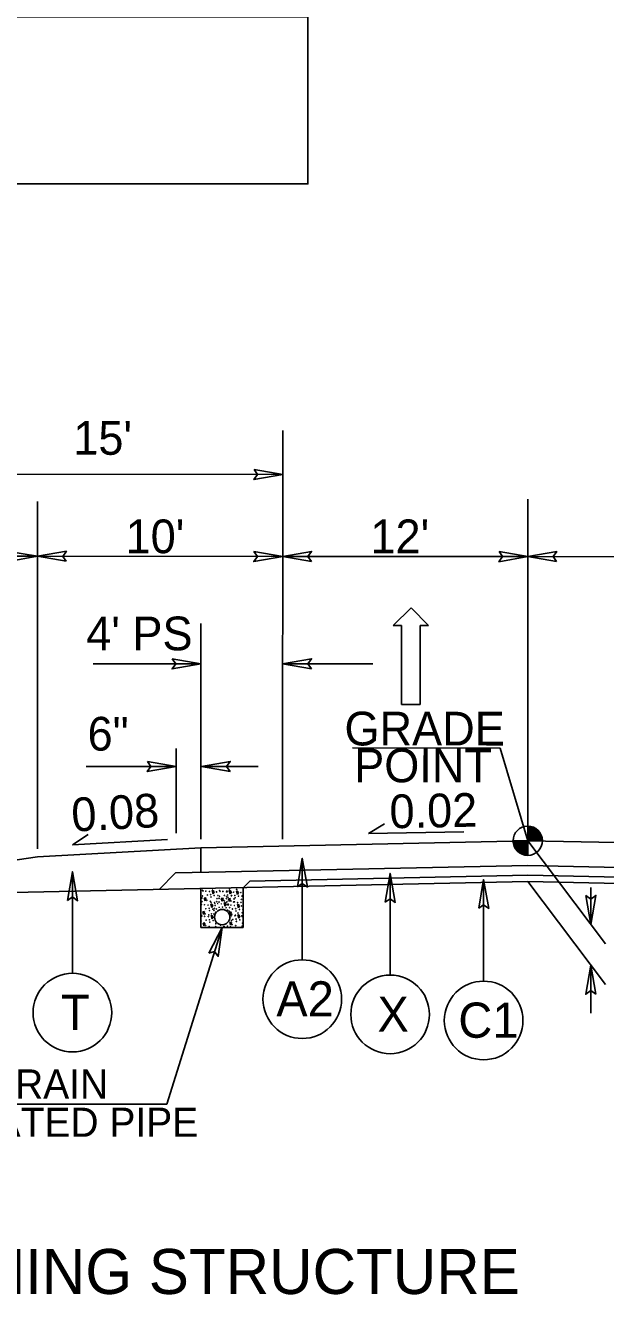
# Model space of a CAD drawing. Extents: x 2241081 to 2251104, y 658534 to 663427.
# Drawn here: x 2243735.8 to 2243877.8, y 662105.6 to 662416.1 of the extents above; entities that cross this region are included whole.
import ezdxf

# ---------------------------------------------------------------- set-up
doc = ezdxf.new("R2010")
doc.units = 0
for name, color, linetype in [('Old_Level_1', 7, 'Continuous'), ('Old_Level_11', 7, 'Continuous'), ('Old_Level_2', 7, 'Continuous'), ('Old_Level_3', 7, 'Continuous'), ('Prop Dimension Text', 7, 'Continuous'), ('Prop Lane Arrow CELL', 7, 'Continuous'), ('Prop Pavement Schedule Description CELL', 7, 'Continuous'), ('Typical Arrow Superelevation CELL', 7, 'Continuous'), ('Typical Berm Information CELL', 7, 'Continuous'), ('Typical Curb CELL', 7, 'Continuous'), ('Typical Grade Point Symbol CELL', 7, 'Continuous'), ('Typical ID Circle CELL', 7, 'Continuous'), ('Typical Terminator CELL', 7, 'Continuous'), ('Typical Text Grade Point CELL', 7, 'Continuous'), ('Typical Text ID Circle CELL', 7, 'Continuous'), ('Typical Text Label CELL', 7, 'Continuous')]:
    doc.layers.add(name, color=color, linetype=linetype)

msp = doc.modelspace()

# ---------------------------------------------------------------- linework, layer by layer
at = {"layer": 'Old_Level_1'}
msp.add_line((2243738.73, 662212.77), (2243713.82, 662209.11), dxfattribs=at)
at = {"layer": 'Old_Level_11'}
msp.add_line((2243770.41, 662152.21), (2243783.94, 662195.49), dxfattribs=at)
at = {"layer": 'Old_Level_2'}
for p, q in [((2243778.73, 662214.97), (2243738.73, 662212.77)), ((2243858.73, 662216.68), (2243778.73, 662214.97)), ((2243778.73, 662214.97), (2243778.73, 662208.92)), ((2243858.73, 662216.68), (2243968.73, 662214.33)), ((2243772.55, 662208.79), (2243768.51, 662204.75)), ((2243784.76, 662209.05), (2243772.55, 662208.79)), ((2243858.73, 662210.63), (2243784.76, 662209.05)), ((2243858.73, 662208.27), (2243790.77, 662206.82)), ((2243858.73, 662210.63), (2243947.95, 662208.72)), ((2243858.73, 662208.27), (2243956.82, 662206.17)), ((2243858.73, 662206.68), (2243713.77, 662203.58)), ((2243778.73, 662204.97), (2243778.73, 662195.49)), ((2243790.77, 662206.82), (2243789.14, 662205.19)), ((2243789.14, 662205.19), (2243789.14, 662195.49)), ((2243858.73, 662206.68), (2243978.95, 662204.11)), ((2243778.73, 662195.49), (2243789.14, 662195.49))]:
    msp.add_line(p, q, dxfattribs=at)
msp.add_circle((2243783.97, 662197.98), 1.87, dxfattribs=at)
at = {"layer": 'Prop Dimension Text'}
for p, q in [((2243798.73, 662217.09), (2243798.79, 662317.04)), ((2243713.79, 662306.33), (2243798.79, 662306.27)), ((2243738.73, 662214.73), (2243738.78, 662299.64)), ((2243858.73, 662214.65), (2243858.78, 662299.57)), ((2243858.78, 662293.47), (2243858.78, 662300.24)), ((2243713.77, 662286.26), (2243738.77, 662286.25)), ((2243738.77, 662286.25), (2243798.77, 662286.21)), ((2243798.77, 662286.21), (2243858.77, 662286.17)), ((2243858.77, 662286.17), (2243918.77, 662286.14)), ((2243778.73, 662217.09), (2243778.76, 662269.78)), ((2243778.76, 662259.95), (2243752.43, 662259.97)), ((2243820.82, 662259.93), (2243798.76, 662259.94)), ((2243772.7, 662218.56), (2243772.7, 662239.22)), ((2243750.69, 662234.84), (2243772.7, 662234.83)), ((2243778.87, 662234.83), (2243792.74, 662234.82)), ((2243858.73, 662216.68), (2243877.74, 662191.47)), ((2243858.73, 662206.68), (2243877.74, 662181.47)), ((2243874.17, 662196.21), (2243874.17, 662205.21)), ((2243874.17, 662174.52), (2243874.17, 662186.21)), ((2243656.74, 662152.28), (2243770.41, 662152.21))]:
    msp.add_line(p, q, dxfattribs=at)
at = {"layer": 'Prop Lane Arrow CELL'}
for p, q in [((2243830.2, 662273.63), (2243825.78, 662269.29)), ((2243834.47, 662269.29), (2243830.2, 662273.63)), ((2243825.78, 662269.29), (2243827.85, 662269.29)), ((2243827.85, 662269.29), (2243827.84, 662250)), ((2243832.39, 662249.99), (2243832.4, 662269.29)), ((2243832.4, 662269.29), (2243834.47, 662269.29)), ((2243827.84, 662250), (2243832.39, 662249.99))]:
    msp.add_line(p, q, dxfattribs=at)
at = {"layer": 'Prop Pavement Schedule Description CELL'}
msp.add_lwpolyline([(2243445.86, 662377.34), (2243404.95, 662377.34), (2243404.95, 662418.25), (2243804.96, 662418.25), (2243804.96, 662377.34), (2243445.86, 662377.34), (2243445.86, 662418.25)], dxfattribs=at)
at = {"layer": 'Typical Arrow Superelevation CELL'}
for p, q in [((2243819.8, 662218.41), (2243823.71, 662220.77)), ((2243747.35, 662215.68), (2243751.18, 662218.18)), ((2243819.8, 662218.41), (2243843.1, 662218.87)), ((2243747.35, 662215.68), (2243770.62, 662216.96))]:
    msp.add_line(p, q, dxfattribs=at)
at = {"layer": 'Typical Curb CELL'}
for p, q in [((2243780, 662202.72), (2243779.56, 662202.63)), ((2243779.56, 662202.63), (2243779.78, 662201.98)), ((2243779.78, 662201.98), (2243780, 662202.72)), ((2243781.54, 662204.61), (2243781.79, 662203.72)), ((2243782.03, 662204.26), (2243781.54, 662204.61)), ((2243781.79, 662203.72), (2243782.03, 662204.26)), ((2243784.17, 662202.66), (2243783.74, 662202.57)), ((2243783.74, 662202.57), (2243783.96, 662201.92)), ((2243783.96, 662201.92), (2243784.17, 662202.66)), ((2243784.44, 662201.59), (2243784.69, 662200.7)), ((2243784.94, 662201.24), (2243784.44, 662201.59)), ((2243785.93, 662202.55), (2243785.5, 662202.47)), ((2243785.5, 662202.47), (2243785.72, 662201.81)), ((2243785.71, 662204.55), (2243785.96, 662203.66)), ((2243786.21, 662204.2), (2243785.71, 662204.55)), ((2243785.72, 662201.81), (2243785.93, 662202.55)), ((2243785.96, 662203.66), (2243786.21, 662204.2)), ((2243787.48, 662204.44), (2243787.73, 662203.55)), ((2243787.97, 662204.09), (2243787.48, 662204.44)), ((2243787.73, 662203.55), (2243787.97, 662204.09)), ((2243779.63, 662199.38), (2243779.2, 662199.3)), ((2243779.2, 662199.3), (2243779.42, 662198.64)), ((2243779.42, 662198.64), (2243779.63, 662199.38)), ((2243781.18, 662201.27), (2243781.43, 662200.38)), ((2243781.67, 662200.92), (2243781.18, 662201.27)), ((2243781.43, 662200.38), (2243781.67, 662200.92)), ((2243784.69, 662200.7), (2243784.94, 662201.24)), ((2243786.14, 662199.29), (2243785.71, 662199.21)), ((2243785.71, 662199.21), (2243785.93, 662198.55)), ((2243785.93, 662198.55), (2243786.14, 662199.29)), ((2243787.68, 662201.18), (2243787.93, 662200.29)), ((2243788.18, 662200.83), (2243787.68, 662201.18)), ((2243787.77, 662198.64), (2243788.02, 662197.75)), ((2243788.26, 662198.29), (2243787.77, 662198.64)), ((2243787.93, 662200.29), (2243788.18, 662200.83)), ((2243779.72, 662196.58), (2243779.29, 662196.49)), ((2243779.29, 662196.49), (2243779.51, 662195.84)), ((2243779.51, 662195.84), (2243779.72, 662196.58)), ((2243781.26, 662198.47), (2243781.51, 662197.58)), ((2243781.76, 662198.12), (2243781.26, 662198.47)), ((2243781.51, 662197.58), (2243781.76, 662198.12)), ((2243786.23, 662196.75), (2243785.8, 662196.67)), ((2243785.8, 662196.67), (2243786.01, 662196.01)), ((2243786.01, 662196.01), (2243786.23, 662196.75)), ((2243788.02, 662197.75), (2243788.26, 662198.29))]:
    msp.add_line(p, q, dxfattribs=at)
for centre in [(2243781.6, 662204.94), (2243785.77, 662204.88), (2243787.53, 662204.77), (2243779.04, 662202.67), (2243779.04, 662201.75), (2243779.13, 662203.15), (2243779.17, 662204.54), (2243779.27, 662204.37), (2243779.97, 662204.34), (2243780.19, 662202.12), (2243780.32, 662203.39), (2243780.87, 662204.26), (2243781.06, 662201.87), (2243781.14, 662203.47), (2243781.22, 662202.9), (2243781.23, 662201.6), (2243782.03, 662203.28), (2243782.6, 662204.15), (2243782.63, 662201.76), (2243782.71, 662202.5), (2243782.9, 662203.31), (2243783.21, 662202.61), (2243783.21, 662201.69), (2243783.31, 662203.09), (2243783.35, 662204.48), (2243783.44, 662204.31), (2243784.15, 662204.28), (2243784.36, 662202.06), (2243784.5, 662203.33), (2243784.5, 662201.92), (2243784.97, 662202.5), (2243784.97, 662201.58), (2243785.04, 662204.2), (2243785.07, 662202.98), (2243785.11, 662204.38), (2243785.2, 662204.2), (2243785.23, 662201.81), (2243785.31, 662203.41), (2243785.39, 662202.84), (2243785.91, 662204.17), (2243786.12, 662201.95), (2243786.21, 662203.22), (2243786.26, 662203.22), (2243786.77, 662204.09), (2243786.8, 662204.09), (2243786.8, 662201.71), (2243786.88, 662202.44), (2243786.99, 662201.71), (2243787.07, 662203.25), (2243787.07, 662203.31), (2243787.15, 662202.74), (2243787.97, 662203.12), (2243788.54, 662203.98), (2243788.56, 662201.6), (2243788.65, 662202.33), (2243788.83, 662203.14), (2243778.81, 662201.21), (2243778.9, 662201.03), (2243779.61, 662201), (2243779.82, 662198.78), (2243779.96, 662200.05), (2243780.5, 662200.92), (2243780.69, 662198.54), (2243780.77, 662200.14), (2243780.85, 662199.57), (2243781.32, 662198.8), (2243781.67, 662199.95), (2243781.94, 662199.66), (2243781.94, 662198.74), (2243782.04, 662200.13), (2243782.08, 662201.53), (2243782.17, 662201.35), (2243782.24, 662200.81), (2243782.34, 662199.16), (2243782.53, 662199.97), (2243782.88, 662201.32), (2243783.23, 662200.38), (2243783.77, 662201.24), (2243784.04, 662200.46), (2243784.12, 662199.89), (2243784.94, 662200.27), (2243785.28, 662199.72), (2243785.32, 662201.12), (2243785.41, 662200.94), (2243785.51, 662201.13), (2243785.61, 662199.48), (2243785.8, 662200.29), (2243786.12, 662200.92), (2243786.33, 662198.69), (2243786.47, 662199.97), (2243787.01, 662200.83), (2243787.2, 662198.45), (2243787.28, 662200.05), (2243787.36, 662199.48), (2243787.74, 662201.51), (2243787.83, 662198.97), (2243788.18, 662199.86), (2243788.74, 662200.73), (2243788.85, 662199.07), (2243789.04, 662199.89), (2243778.85, 662197.01), (2243778.9, 662198.4), (2243778.99, 662198.23), (2243779.69, 662198.2), (2243779.91, 662195.98), (2243780.05, 662197.25), (2243780.59, 662198.12), (2243780.78, 662195.73), (2243780.86, 662197.33), (2243780.94, 662196.76), (2243781.75, 662197.14), (2243782.35, 662195.63), (2243782.41, 662196.53), (2243782.41, 662195.61), (2243782.43, 662196.36), (2243783.56, 662195.98), (2243784.43, 662195.73), (2243785.27, 662195.79), (2243785.97, 662198.01), (2243786, 662195.63), (2243786.08, 662196.36), (2243786.2, 662198.37), (2243786.27, 662197.17), (2243786.42, 662196.15), (2243786.56, 662197.43), (2243787.1, 662198.29), (2243787.29, 662195.91), (2243787.37, 662197.51), (2243787.45, 662196.94), (2243788.26, 662197.32), (2243788.77, 662198.34), (2243788.83, 662198.18), (2243788.86, 662195.8), (2243788.94, 662196.53)]:
    msp.add_circle(centre, 0.0381, dxfattribs=at)
at = {"layer": 'Typical Grade Point Symbol CELL'}
for p, q in [((2243858.73, 662216.68), (2243852, 662239.35)), ((2243858.74, 662220.26), (2243858.73, 662216.68)), ((2243858.73, 662216.68), (2243858.74, 662220.26)), ((2243855.15, 662216.68), (2243858.73, 662216.68)), ((2243858.73, 662216.68), (2243858.73, 662213.1)), ((2243862.31, 662216.68), (2243858.73, 662216.68))]:
    msp.add_line(p, q, dxfattribs=at)
for points in [[(2243858.79, 662216.68), (2243858.79, 662220.26), (2243858.79, 662220.26)], [(2243858.86, 662216.68), (2243858.86, 662220.26)], [(2243858.93, 662216.68), (2243858.93, 662220.26)], [(2243859, 662216.68), (2243859, 662220.26)], [(2243859.07, 662216.68), (2243859.07, 662220.25)], [(2243859.15, 662216.68), (2243859.15, 662220.24)], [(2243859.22, 662216.68), (2243859.22, 662220.23)], [(2243859.29, 662216.68), (2243859.29, 662220.22)], [(2243859.36, 662216.68), (2243859.36, 662220.21)], [(2243859.43, 662216.68), (2243859.43, 662220.19)], [(2243859.5, 662216.68), (2243859.5, 662220.18)], [(2243859.58, 662216.68), (2243859.58, 662220.16)], [(2243859.65, 662216.68), (2243859.65, 662220.14)], [(2243859.72, 662216.68), (2243859.72, 662220.12)], [(2243859.79, 662216.68), (2243859.79, 662220.1)], [(2243859.86, 662216.68), (2243859.86, 662220.08)], [(2243859.93, 662216.68), (2243859.93, 662220.06)], [(2243860, 662216.68), (2243860, 662220.03)], [(2243860.08, 662216.68), (2243860.08, 662220)], [(2243860.15, 662216.68), (2243860.15, 662219.97)], [(2243860.22, 662216.68), (2243860.22, 662219.94)], [(2243860.29, 662216.68), (2243860.29, 662219.91)], [(2243860.36, 662216.68), (2243860.36, 662219.87)], [(2243860.43, 662216.68), (2243860.43, 662219.83)], [(2243860.51, 662216.68), (2243860.51, 662219.79)], [(2243860.58, 662216.68), (2243860.58, 662219.75)], [(2243860.65, 662216.68), (2243860.65, 662219.71)], [(2243860.72, 662216.68), (2243860.72, 662219.66)], [(2243860.79, 662216.68), (2243860.79, 662219.61)], [(2243860.86, 662216.68), (2243860.86, 662219.56)], [(2243860.94, 662216.68), (2243860.94, 662219.51)], [(2243861.01, 662216.68), (2243861.01, 662219.45)], [(2243861.08, 662216.68), (2243861.08, 662219.39)], [(2243861.15, 662216.68), (2243861.15, 662219.32)], [(2243861.22, 662216.68), (2243861.22, 662219.26)], [(2243861.29, 662216.68), (2243861.29, 662219.19)], [(2243861.37, 662216.68), (2243861.37, 662219.11)], [(2243861.44, 662216.68), (2243861.44, 662219.03)], [(2243861.51, 662216.68), (2243861.51, 662218.94)], [(2243861.58, 662216.68), (2243861.58, 662218.85)], [(2243861.65, 662216.68), (2243861.65, 662218.76)], [(2243861.72, 662216.68), (2243861.72, 662218.66)], [(2243861.8, 662216.68), (2243861.8, 662218.54)], [(2243861.87, 662216.68), (2243861.87, 662218.42)], [(2243861.94, 662216.68), (2243861.94, 662218.28)], [(2243862.01, 662216.68), (2243862.01, 662218.13)], [(2243862.08, 662216.68), (2243862.08, 662217.96)], [(2243862.15, 662216.68), (2243862.15, 662217.75)], [(2243862.23, 662216.68), (2243862.23, 662217.49)], [(2243855.19, 662216.17), (2243855.19, 662216.68)], [(2243855.26, 662215.81), (2243855.26, 662216.68)], [(2243855.33, 662215.56), (2243855.33, 662216.68)], [(2243855.41, 662215.36), (2243855.41, 662216.68)], [(2243855.48, 662215.19), (2243855.48, 662216.68)], [(2243855.55, 662215.04), (2243855.55, 662216.68)], [(2243855.62, 662214.92), (2243855.62, 662216.68)], [(2243855.69, 662214.8), (2243855.69, 662216.68)], [(2243855.76, 662214.69), (2243855.76, 662216.68)], [(2243855.84, 662214.58), (2243855.84, 662216.68)], [(2243855.91, 662214.49), (2243855.91, 662216.68)], [(2243855.98, 662214.4), (2243855.98, 662216.68)], [(2243856.05, 662214.31), (2243856.05, 662216.68)], [(2243856.12, 662214.23), (2243856.12, 662216.68)], [(2243856.19, 662214.16), (2243856.19, 662216.68)], [(2243856.27, 662214.09), (2243856.27, 662216.68)], [(2243856.34, 662214.02), (2243856.34, 662216.68)], [(2243856.41, 662213.96), (2243856.41, 662216.68)], [(2243856.48, 662213.9), (2243856.48, 662216.68)], [(2243856.55, 662213.84), (2243856.55, 662216.68)], [(2243856.62, 662213.79), (2243856.62, 662216.68)], [(2243856.69, 662213.74), (2243856.69, 662216.68)], [(2243856.77, 662213.69), (2243856.77, 662216.68)], [(2243856.84, 662213.64), (2243856.84, 662216.68)], [(2243856.91, 662213.6), (2243856.91, 662216.68)], [(2243856.98, 662213.56), (2243856.98, 662216.68)], [(2243857.05, 662213.52), (2243857.05, 662216.68)], [(2243857.12, 662213.48), (2243857.12, 662216.68)], [(2243857.2, 662213.45), (2243857.2, 662216.68)], [(2243857.27, 662213.42), (2243857.27, 662216.68)], [(2243857.34, 662213.39), (2243857.34, 662216.68)], [(2243857.41, 662213.36), (2243857.41, 662216.68)], [(2243857.48, 662213.32), (2243857.48, 662216.68)], [(2243857.55, 662213.3), (2243857.55, 662216.68)], [(2243857.63, 662213.28), (2243857.63, 662216.68)], [(2243857.7, 662213.25), (2243857.7, 662216.68)], [(2243857.77, 662213.24), (2243857.77, 662216.68)], [(2243857.84, 662213.21), (2243857.84, 662216.68)], [(2243857.91, 662213.2), (2243857.91, 662216.68)], [(2243857.98, 662213.18), (2243857.98, 662216.68)], [(2243858.06, 662213.17), (2243858.06, 662216.68)], [(2243858.13, 662213.15), (2243858.13, 662216.68)], [(2243858.2, 662213.14), (2243858.2, 662216.68)], [(2243858.27, 662213.13), (2243858.27, 662216.68)], [(2243858.34, 662213.13), (2243858.34, 662216.68)], [(2243858.41, 662213.12), (2243858.41, 662216.68)], [(2243858.49, 662213.11), (2243858.49, 662216.68)], [(2243858.56, 662213.11), (2243858.56, 662216.68)], [(2243858.63, 662213.1), (2243858.63, 662216.68)], [(2243858.7, 662213.1), (2243858.7, 662213.1), (2243858.7, 662216.68)], [(2243862.3, 662216.68), (2243862.3, 662217.07)]]:
    msp.add_lwpolyline(points, dxfattribs=at)
msp.add_circle((2243858.74, 662216.68), 3.58, dxfattribs=at)
for start, end in [(359.9905, 89.9905), (179.9905, 269.9905)]:
    msp.add_arc((2243858.74, 662216.68), 3.58, start, end, dxfattribs=at)
at = {"layer": 'Typical ID Circle CELL'}
for p, q in [((2243803.57, 662187.53), (2243803.57, 662212.39)), ((2243747.32, 662184.23), (2243747.32, 662209.08)), ((2243825.06, 662183.81), (2243825.06, 662208.66)), ((2243847.95, 662182.33), (2243847.95, 662207.18))]:
    msp.add_line(p, q, dxfattribs=at)
for centre in [(2243803.57, 662177.92), (2243747.32, 662174.62), (2243825.06, 662174.2), (2243847.95, 662172.71)]:
    msp.add_circle(centre, 9.62, dxfattribs=at)
at = {"layer": 'Typical Terminator CELL'}
for points in [[(2243791.76, 662307.49), (2243798.79, 662306.27), (2243791.72, 662305.03), (2243792.62, 662306.28)], [(2243731.74, 662287.46), (2243738.77, 662286.25), (2243731.7, 662285), (2243732.6, 662286.25)], [(2243745.8, 662285.03), (2243738.77, 662286.25), (2243745.84, 662287.49), (2243744.95, 662286.24)], [(2243791.74, 662287.43), (2243798.77, 662286.21), (2243791.7, 662284.97), (2243792.6, 662286.22)], [(2243805.8, 662285), (2243798.77, 662286.21), (2243805.84, 662287.46), (2243804.95, 662286.21)], [(2243851.74, 662287.39), (2243858.77, 662286.17), (2243851.7, 662284.93), (2243852.6, 662286.18)], [(2243865.8, 662284.96), (2243858.77, 662286.17), (2243865.84, 662287.42), (2243864.95, 662286.17)], [(2243771.73, 662261.17), (2243778.76, 662259.95), (2243771.69, 662258.71), (2243772.59, 662259.96)], [(2243805.79, 662258.73), (2243798.76, 662259.94), (2243805.83, 662261.19), (2243804.93, 662259.94)], [(2243765.67, 662236.05), (2243772.7, 662234.83), (2243765.63, 662233.59), (2243766.53, 662234.83)], [(2243785.9, 662233.61), (2243778.87, 662234.83), (2243785.94, 662236.07), (2243785.04, 662234.82)], [(2243802.36, 662205.36), (2243803.57, 662212.39), (2243804.82, 662205.32), (2243803.57, 662206.22)], [(2243746.11, 662202.05), (2243747.32, 662209.08), (2243748.57, 662202.01), (2243747.32, 662202.91)], [(2243823.85, 662201.63), (2243825.06, 662208.66), (2243826.31, 662201.59), (2243825.06, 662202.49)], [(2243846.74, 662200.15), (2243847.95, 662207.18), (2243849.2, 662200.11), (2243847.95, 662201.01)], [(2243872.96, 662203.24), (2243874.17, 662196.21), (2243875.42, 662203.28), (2243874.17, 662202.39)], [(2243780.68, 662189.14), (2243783.94, 662195.49), (2243783.02, 662188.37), (2243782.1, 662189.6)], [(2243875.38, 662179.18), (2243874.17, 662186.21), (2243872.92, 662179.14), (2243874.17, 662180.04)]]:
    msp.add_lwpolyline(points, close=True, dxfattribs=at)
at = {"layer": 'Typical Text Grade Point CELL'}
msp.add_line((2243852, 662239.35), (2243815.87, 662239.37), dxfattribs=at)

# ---------------------------------------------------------------- texts
at = {"layer": 'Old_Level_3'}
for s, p in [('12"x12" SHLD. DRAIN', (2243660.26, 662153.6)), ('W/  4" PERFORATED PIPE', (2243660.26, 662144.25))]:
    msp.add_text(s, height=7.1311, rotation=359.9999, dxfattribs=at).set_placement(p)
at = {"layer": 'Prop Dimension Text'}
for s, p in [("15'", (2243747.53, 662311.09)), ("10'", (2243760.33, 662287.01)), ("12'", (2243820.25, 662287.01)), ("4' PS", (2243750.69, 662263.27)), ('6"', (2243751.02, 662238.72))]:
    msp.add_text(s, height=8.25, rotation=359.965, dxfattribs=at).set_placement(p)
at = {"layer": 'Typical Berm Information CELL'}
for s, rotation, p in [('0.08', 3.1445, (2243747.29, 662218.88)), ('0.02 ', 1.1459, (2243824.99, 662219.7))]:
    msp.add_text(s, height=8.25, rotation=rotation, dxfattribs=at).set_placement(p)
at = {"layer": 'Typical Text Grade Point CELL'}
for s, p in [('GRADE', (2243813.89, 662239.99)), ('POINT', (2243816.27, 662230.98))]:
    msp.add_text(s, height=8.25, rotation=359.965, dxfattribs=at).set_placement(p)
at = {"layer": 'Typical Text ID Circle CELL'}
for s, height, p in [('A2', 8.608, (2243797.21, 662173.68)), ('T', 8.61, (2243744.5, 662170.38)), ('X', 8.61, (2243821.96, 662169.96)), ('C1', 8.608, (2243841.76, 662168.48))]:
    msp.add_text(s, height=height, rotation=359.9999, dxfattribs=at).set_placement(p)
at = {"layer": 'Typical Text Label CELL'}
msp.add_text('TYPICAL APPROACHING STRUCTURE', height=11.0106, dxfattribs=at).set_placement((2243587.65, 662105.8))

doc.saveas('drawing.dxf')
